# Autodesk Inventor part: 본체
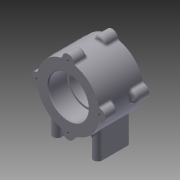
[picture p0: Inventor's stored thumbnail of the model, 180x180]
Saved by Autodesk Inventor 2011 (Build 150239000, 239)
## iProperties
Created: 2015-03
Part Number: 본체
Document SubType Name: Modeling
Designer: Administrator
Density: 2.71 g/cm^3
Material: 알루미늄-6061
Mass: 450.776 g
Surface Area: 332.709 cm^2
Volume: 166.338 cm^3
Author: Administrator
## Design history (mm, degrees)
sketch "스케치1"
  geometry: L1 (24, -20)-(24, 20) reference; L2 (-24, 20)-(-24, -20) reference; L3 (29, -15)-(29, 15); L4 (19, -15)-(19, 15); L5 (-19, 15)-(-19, -15); L6 (-29, 15)-(-29, -15); L7 (24, -20)-(24, -20); L8 (-24, -20)-(-24, -20); L9 (-24, 20)-(-24, 20); L10 (24, 20)-(24, 20); A1 r 5 centre (-24, 15) between (-24, 20) and (-29, 15); A2 r 5 centre (-24, 15) between (-19, 15) and (-24, 20); A3 r 5 centre (-24, -15) between (-29, -15) and (-24, -20); A4 r 5 centre (-24, -15) between (-24, -20) and (-19, -15); A5 r 5 centre (24, -15) between (19, -15) and (24, -20); A6 r 5 centre (24, -15) between (24, -20) and (29, -15); A7 r 5 centre (24, 15) between (29, 15) and (24, 20); A8 r 5 centre (24, 15) between (24, 20) and (19, 15); 3 further points
  constraints: 20 end point, 16 point on circle, 16 tangent, 9 parallel, 8 centre point, 7 equal radius, 2 perpendicular, 2 vertical, 1 horizontal alignment, 1 midpoint, 1 vertical alignment
  dimensions: "d2" = 5 distance between parallel lines of L1 L4; "d3" = 5 distance between parallel lines of L3 L1; "d4" = 5 distance between parallel lines of L2 L6; "d5" = 5 distance between parallel lines of L5 L2; "d6" = 5 radius of A1
extrude "돌출1" new body sketch "스케치1" distance "d7" = 56; taper "d8" = 0 deg
sketch "스케치2"
  geometry: L1 (15, 56)-(-15, 56) reference; L2 (-15, 0)-(-15, 56) reference; L3 (15, 0)-(-15, 0) reference; L4 (15, 0)-(15, 56) reference; L5 (0, 56)-(-26, 56); L6 (-26, 56)-(-26, 93); L7 (-26, 93)-(26, 93); L8 (26, 93)-(26, 56); L9 (26, 56)-(0, 56); 1 further point
  constraints: 10 end point, 2 point on line, 1 collinear, 1 midpoint, 1 parallel, 1 perpendicular
revolve "회전1" sketch "스케치2" stored, may be unused: angle "d9" = 90 deg
sketch "스케치3"
  geometry: C1 r 37 at (0, 0) reference; C2 r 23.5 at (0, 0); 1 further point
  constraints: 1 centre point, 1 coincident
extrude "돌출2" cut sketch "스케치3" distance "d10" = 22; taper "d11" = 0 deg
sketch "스케치4"
  geometry: C1 r 37 at (0, 0) reference; C2 r 23.5 at (0, 0); 1 further point
  constraints: 1 centre point, 1 coincident
extrude "돌출3" cut sketch "스케치4" distance "d12" = 22; taper "d13" = 0 deg
sketch "스케치5"
  geometry: C1 r 23.5 at (0, 0) reference; C2 r 21 at (0, 0); 1 further point
  constraints: 1 centre point, 1 coincident
extrude "돌출4" cut sketch "스케치5" stored distance "d14" = 22; taper "d15" = 0 deg
fillet "모깎기1" dims "d16" = 3
sketch "스케치6"
  geometry: A1 r 7 centre (0, 37) between (6.969, 36.338) and (-6.969, 36.338); A2 r 7 centre (-37, 0) between (-36.338, 6.969) and (-36.338, -6.969); A3 r 7 centre (0, -37) between (-6.969, -36.338) and (6.969, -36.338); A4 r 7 centre (37, 0) between (36.338, -6.969) and (36.338, 6.969); 2 further points
  constraints: 8 point on circle, 4 centre point, 13 other
extrude "돌출5" join sketch "스케치6" distance "d17" = 15; taper "d18" = 0 deg
fillet "모깎기2" dims "d19" = 3
fillet "모깎기3" dims "d20" = 3
chamfer "모따기1" distance "d21" = 1; stored, may be unused: second distance "d22" = 2, angle "d23" = 45 deg
fillet "모깎기4" dims "d24" = 0.3
sketch "스케치7"
  geometry: A1 r 7 centre (-37, 37) between (-38.239, 43.889) and (-38.239, 30.111) reference; A2 r 7 centre (0, 0) between (-6.889, -1.239) and (6.889, -1.239) reference; A3 r 7 centre (37, 37) between (38.239, 30.111) and (38.239, 43.889) reference; A4 r 7 centre (0, 74) between (6.889, 75.239) and (-6.889, 75.239) reference; 5 further points
  constraints: 4 coincident
hole "Hole1" sketch "스케치7" at (0, 74), (-37, 37), (0, 0), (37, 37) diameter "d25" = 3.242; stored, may be unused: countersink angle "d29" = 90 deg, drill point angle "d31" = 118 deg; dims "d26" = 8, "d27" = 4, "d28" = 2, "d30" = 11
sketch "스케치8"
  geometry: A1 r 7 centre (37, -37) between (38.239, -43.889) and (38.239, -30.111) reference; A2 r 7 centre (0, 0) between (6.889, 1.239) and (-6.889, 1.239) reference; A3 r 7 centre (-37, -37) between (-38.239, -30.111) and (-38.239, -43.889) reference; A4 r 7 centre (0, -74) between (-6.889, -75.239) and (6.889, -75.239) reference; 5 further points
  constraints: 4 coincident
hole "Hole2" sketch "스케치8" at (0, 0), (-37, -37), (0, -74), (37, -37) diameter "d32" = 3.242; stored, may be unused: countersink angle "d36" = 90 deg, drill point angle "d38" = 118 deg; dims "d33" = 8, "d34" = 4, "d35" = 2, "d37" = 11
sketch "스케치9"
  geometry: L1 (-19, -15)-(-19, 15) reference; L2 (-29, 15)-(-29, -15) reference; A1 r 5 centre (24, 15) between (29, 15) and (19, 15) reference; A2 r 5 centre (24, -15) between (19, -15) and (29, -15) reference; A3 r 5 centre (-24, 15) between (-19, 15) and (-29, 15) reference; A4 r 5 centre (-24, -15) between (-29, -15) and (-19, -15) reference; 5 further points
  constraints: 4 coincident
hole "Hole3" sketch "스케치9" at (-24, 15), (-24, -15), (24, -15), (24, 15) diameter "d39" = 4.134; stored, may be unused: countersink angle "d43" = 90 deg, drill point angle "d45" = 118 deg; dims "d40" = 6, "d41" = 4, "d42" = 2, "d44" = 8
node "작업 평면2"
  node "작업 평면1"
sketch "스케치10"
  geometry: L1 (-20.388, 2.814)-(21.091, 2.814); L2 (21.091, 2.814)-(21.091, -3.19); L3 (21.091, -3.19)-(-20.388, -3.19); L4 (-20.388, -3.19)-(-20.388, 2.814); L5 (-26, 18.921)-(-26, -18.921) reference; L6 (-26, 0)-(0, 0); 1 further point
  constraints: 2 end point, 1 midpoint, 1 perpendicular, 2 other
feature "엠보싱1" sketch "스케치10" dims "d2" = 5, "d3" = 5, "d4" = 5, "d5" = 5, "d6" = 5, "d47" = 0.5, "d48" = 0
node "솔리드1"
mirror "대칭1"
node "투영된 루프1"
node "투영된 루프2"
node "작업축1"
other parameters: "d46" = 45 deg
